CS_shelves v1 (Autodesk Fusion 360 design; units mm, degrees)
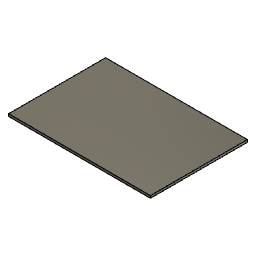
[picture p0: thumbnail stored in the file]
sketch "Sketch1" plane through (0, 0, 0) normal (0, 1, 0) x axis (1, 0, 0)
  line L1 (586, 0) -> (0, 0)
  line L2 (586, 401) -> (586, 0)
  line L3 (0, 401) -> (586, 401)
  line L4 (0, 0) -> (0, 401)
  point P1 (0, 0)
  point P2 (0, 0)
  point P3 (586, 0)
  point P5 (0, 401)
  horizontal L1
  vertical L2
  horizontal L3
  vertical L4
  coincident P1 P2
  dimension "d1" distance P2 P3 = 586
  dimension "d2" distance P2 P5 = 401
extrude "Extrude1" new body sketch "Sketch1" along normal blind 9.6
